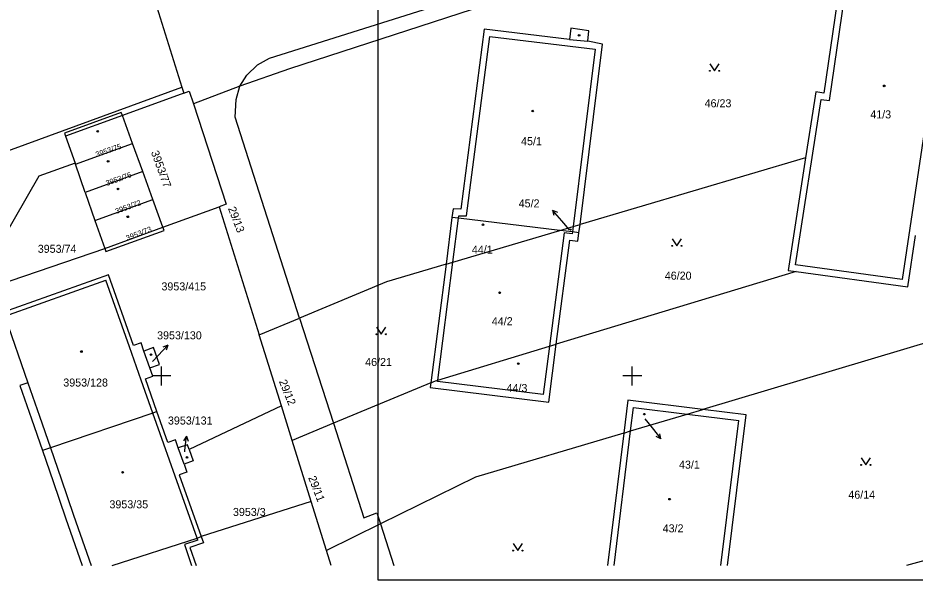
# Model space of a CAD drawing. Extents: x -599970 to -599524, y -1154772 to -1154457.
# Drawn here: x -599915.3 to -599820, y -1154771.7 to -1154712 of the extents above; entities that cross this region are included whole.
import ezdxf

# ---------------------------------------------------------------- set-up
doc = ezdxf.new("R2010")
doc.units = 0
for name, color, linetype in [('Z-KATASTRALNI MAPA', 7, 'Continuous'), ('Z-KRIZKY CTVERCOVE SITE', 7, 'Continuous'), ('Z-RAM ROZPISKA', 7, 'Continuous')]:
    doc.layers.add(name, color=color, linetype=linetype)

msp = doc.modelspace()

# ---------------------------------------------------------------- linework, layer by layer
at = {"layer": 'Z-KATASTRALNI MAPA'}
for p, q in [((-599829.05, -1154720.77), (-599826.27, -1154701.73)), ((-599900.66, -1154710.3), (-599897.83, -1154719.36)), ((-599867.61, -1154733.02), (-599865.13, -1154713.98)), ((-599865.13, -1154713.98), (-599853.93, -1154715.33)), ((-599856.68, -1154714.3), (-599854.73, -1154714.47)), ((-599853.93, -1154715.33), (-599856.28, -1154734.14)), ((-599897.64, -1154719.98), (-599904.16, -1154722.36)), ((-599897.83, -1154719.36), (-599897.64, -1154719.98)), ((-599891.67, -1154719.24), (-599896.62, -1154721.12)), ((-599832.65, -1154738.2), (-599829.92, -1154720.65)), ((-599829.92, -1154720.65), (-599829.05, -1154720.77)), ((-599904.16, -1154722.36), (-599910.2, -1154724.56)), ((-599903.08, -1154725.33), (-599904.16, -1154722.36)), ((-599818.78, -1154722.72), (-599821.34, -1154739.76)), ((-599909.15, -1154727.54), (-599903.08, -1154725.33)), ((-599902, -1154728.29), (-599903.08, -1154725.33)), ((-599909.15, -1154727.54), (-599909.19, -1154727.43)), ((-599908.11, -1154730.52), (-599909.15, -1154727.54)), ((-599831.6, -1154726.85), (-599855.55, -1154733.93)), ((-599902, -1154728.29), (-599908.11, -1154730.52)), ((-599900.93, -1154731.26), (-599902, -1154728.29)), ((-599908.11, -1154730.52), (-599907.07, -1154733.49)), ((-599907.07, -1154733.49), (-599900.93, -1154731.26)), ((-599899.85, -1154734.22), (-599900.93, -1154731.26)), ((-599899.85, -1154734.22), (-599893.87, -1154732.04)), ((-599893.87, -1154732.04), (-599889.62, -1154745.65)), ((-599857.49, -1154733.53), (-599858.475, -1154732.397)), ((-599858.475, -1154732.397), (-599857.957, -1154732.611)), ((-599858.475, -1154732.397), (-599858.335, -1154732.94)), ((-599869.15, -1154733.18), (-599869.78, -1154738.13)), ((-599869.05, -1154737.91), (-599868.46, -1154733.26)), ((-599868.46, -1154733.26), (-599868.42, -1154732.99)), ((-599868.42, -1154732.99), (-599867.61, -1154733.02)), ((-599907.07, -1154733.49), (-599906.02, -1154736.47)), ((-599906.02, -1154736.47), (-599899.85, -1154734.22)), ((-599856.68, -1154734.48), (-599857.49, -1154733.53)), ((-599856.28, -1154734.14), (-599856.35, -1154734.72)), ((-599855.66, -1154734.8), (-599855.55, -1154733.93)), ((-599857.25, -1154734.82), (-599858.81, -1154746.85)), ((-599856.38, -1154734.93), (-599857.25, -1154734.82)), ((-599856.35, -1154734.72), (-599856.38, -1154734.93)), ((-599917.6, -1154740.42), (-599906.02, -1154736.47)), ((-599869.78, -1154738.13), (-599876.11, -1154740)), ((-599869.78, -1154738.13), (-599871.4, -1154750.71)), ((-599870.66, -1154750.43), (-599869.05, -1154737.91)), ((-599821.34, -1154739.76), (-599832.65, -1154738.2)), ((-599832.6, -1154738.92), (-599858.08, -1154746.63)), ((-599905.63, -1154739.27), (-599916.8, -1154743.23)), ((-599916.65, -1154743.66), (-599905.91, -1154739.85)), ((-599903.4, -1154746.92), (-599905.91, -1154739.85)), ((-599876.11, -1154740), (-599885.34, -1154743.86)), ((-599889.62, -1154745.65), (-599885.34, -1154743.86)), ((-599885.34, -1154743.86), (-599881.75, -1154755.01)), ((-599812.77, -1154744.68), (-599842.5, -1154753.54)), ((-599887.27, -1154753.17), (-599889.62, -1154745.65)), ((-599900.37, -1154747.83), (-599899.346, -1154746.732)), ((-599899.346, -1154746.732), (-599899.872, -1154746.928)), ((-599899.346, -1154746.732), (-599899.505, -1154747.269)), ((-599858.81, -1154746.85), (-599858.08, -1154746.63)), ((-599902.15, -1154750.46), (-599903.4, -1154746.92)), ((-599901.24, -1154749.14), (-599901.87, -1154747.35)), ((-599858.81, -1154746.85), (-599859.48, -1154751.98)), ((-599900.96, -1154748.47), (-599900.37, -1154747.83)), ((-599900.92, -1154753.93), (-599902.15, -1154750.46)), ((-599871.4, -1154750.71), (-599870.91, -1154750.51)), ((-599870.68, -1154750.6), (-599870.66, -1154750.43)), ((-599859.48, -1154751.98), (-599870.68, -1154750.6)), ((-599914.2, -1154750.72), (-599912.97, -1154754.26)), ((-599871.4, -1154750.71), (-599881.75, -1154755.01)), ((-599887.27, -1154753.17), (-599897.06, -1154757.81)), ((-599886.13, -1154756.83), (-599887.27, -1154753.17)), ((-599850.18, -1154755.83), (-599849.87, -1154753.34)), ((-599849.87, -1154753.34), (-599844.17, -1154754.04)), ((-599912.97, -1154754.26), (-599911.8, -1154757.63)), ((-599899.75, -1154757.22), (-599900.92, -1154753.93)), ((-599844.17, -1154754.04), (-599838.68, -1154754.72)), ((-599881.75, -1154755.01), (-599886.13, -1154756.83)), ((-599848.65, -1154754.53), (-599847.89, -1154755.49)), ((-599840.58, -1154770.1), (-599838.68, -1154754.72)), ((-599850.91, -1154756.05), (-599866.67, -1154760.75)), ((-599851.94, -1154770.1), (-599850.18, -1154755.83)), ((-599847.89, -1154755.49), (-599846.966, -1154756.673)), ((-599846.966, -1154756.673), (-599847.077, -1154756.123)), ((-599898.54, -1154760.63), (-599899.75, -1154757.22)), ((-599897.363, -1154756.397), (-599897.664, -1154756.87)), ((-599897.52, -1154757.89), (-599897.363, -1154756.397)), ((-599897.363, -1154756.397), (-599897.167, -1154756.922)), ((-599884.11, -1154763.3), (-599886.13, -1154756.83)), ((-599846.966, -1154756.673), (-599847.472, -1154756.432)), ((-599911.8, -1154757.63), (-599910.66, -1154760.9)), ((-599897.61, -1154759.36), (-599898.22, -1154757.63)), ((-599897.54, -1154758.06), (-599897.52, -1154757.89)), ((-599910.66, -1154760.9), (-599909.34, -1154764.77)), ((-599896.21, -1154767.19), (-599898.54, -1154760.63)), ((-599866.67, -1154760.75), (-599876.75, -1154765.7)), ((-599884.11, -1154763.3), (-599895.79, -1154767.04)), ((-599882.48, -1154768.52), (-599884.11, -1154763.3)), ((-599909.34, -1154764.77), (-599907.46, -1154770.1)), ((-599876.75, -1154765.7), (-599882.48, -1154768.52)), ((-599896.13, -1154767.43), (-599897.56, -1154767.89)), ((-599896.13, -1154767.43), (-599896.21, -1154767.19)), ((-599897.56, -1154767.89), (-599896.8, -1154770.1)), ((-599881.99, -1154770.1), (-599882.48, -1154768.52)), ((-599817.19, -1154769.12), (-599820.88, -1154770.1))]:
    msp.add_line(p, q, dxfattribs=at)
for points in [[(-599891.67, -1154719.24), (-599890.93, -1154718.08), (-599889.79, -1154717), (-599888.53, -1154716.29), (-599840.69, -1154701.22)], [(-599833.96, -1154702.4), (-599865.59, -1154710.66), (-599886.42, -1154717.4), (-599891.67, -1154719.24)], [(-599827.27, -1154703.72), (-599829.64, -1154719.98), (-599830.51, -1154719.86), (-599830.65, -1154720.78), (-599831.6, -1154726.85)], [(-599856.68, -1154714.3), (-599865.74, -1154713.21), (-599868.22, -1154732.3), (-599869.03, -1154732.27), (-599869.15, -1154733.18)], [(-599854.73, -1154714.47), (-599854.63, -1154713.38), (-599856.53, -1154713.11), (-599856.68, -1154714.3)], [(-599855.55, -1154733.93), (-599853.16, -1154714.78), (-599854.73, -1154714.47)], [(-599841.76, -1154716.87), (-599841.26, -1154717.62), (-599840.76, -1154716.87)], [(-599926.88, -1154737.29), (-599920.92, -1154735.02), (-599917.44, -1154726.5), (-599897.83, -1154719.36)], [(-599897.64, -1154719.98), (-599897.06, -1154719.77), (-599896.62, -1154721.12)], [(-599885.34, -1154743.86), (-599892.18, -1154722.54), (-599892.08, -1154720.65), (-599891.67, -1154719.24)], [(-599896.62, -1154721.12), (-599893.12, -1154731.77), (-599893.87, -1154732.04)], [(-599904.16, -1154722.36), (-599904.28, -1154722.03), (-599910.32, -1154724.23), (-599910.2, -1154724.56), (-599909.19, -1154727.43)], [(-599909.19, -1154727.43), (-599913.05, -1154728.79), (-599918.31, -1154737.91)], [(-599831.6, -1154726.85), (-599833.45, -1154738.8), (-599832.6, -1154738.92)], [(-599857.69, -1154734.56), (-599868.46, -1154733.26), (-599869.15, -1154733.18)], [(-599906.02, -1154736.47), (-599905.9, -1154736.8), (-599899.73, -1154734.55), (-599899.85, -1154734.22)], [(-599857.69, -1154734.56), (-599856.28, -1154734.14), (-599855.55, -1154733.93)], [(-599869.78, -1154738.13), (-599869.05, -1154737.91), (-599857.69, -1154734.56)], [(-599858.08, -1154746.63), (-599856.65, -1154735.6), (-599855.77, -1154735.71), (-599855.66, -1154734.8)], [(-599855.66, -1154734.8), (-599856.35, -1154734.72), (-599857.69, -1154734.56)], [(-599832.6, -1154738.92), (-599820.75, -1154740.54), (-599819.93, -1154735.08)], [(-599845.76, -1154735.44), (-599845.26, -1154736.19), (-599844.76, -1154735.44)], [(-599901.87, -1154747.35), (-599902.17, -1154746.48), (-599902.98, -1154746.77), (-599905.63, -1154739.27)], [(-599916.65, -1154743.66), (-599914.2, -1154750.72), (-599915.05, -1154751.02), (-599913.82, -1154754.56), (-599912.66, -1154757.92)], [(-599877.17, -1154744.819), (-599876.67, -1154745.57), (-599876.17, -1154744.819)], [(-599871.4, -1154750.71), (-599871.46, -1154751.21), (-599858.88, -1154752.76), (-599858.08, -1154746.63)], [(-599901.24, -1154749.14), (-599900.21, -1154748.78), (-599900.84, -1154746.99), (-599901.87, -1154747.35)], [(-599870.91, -1154750.51), (-599870.66, -1154750.43), (-599858.81, -1154746.85)], [(-599900.49, -1154753.78), (-599901.72, -1154750.31), (-599900.93, -1154750.03), (-599901.24, -1154749.14)], [(-599842.5, -1154753.54), (-599850.48, -1154752.56), (-599850.91, -1154756.05)], [(-599900.49, -1154753.78), (-599900.92, -1154753.93), (-599911.8, -1154757.63), (-599912.66, -1154757.92)], [(-599898.22, -1154757.63), (-599898.52, -1154756.79), (-599899.32, -1154757.07), (-599900.49, -1154753.78)], [(-599850.91, -1154756.05), (-599850.18, -1154755.83), (-599844.17, -1154754.04), (-599842.5, -1154753.54)], [(-599839.88, -1154770.1), (-599837.9, -1154754.11), (-599842.5, -1154753.54)], [(-599881.75, -1154755.01), (-599878.53, -1154765.05), (-599877.13, -1154764.51), (-599876.75, -1154765.7)], [(-599850.91, -1154756.05), (-599852.64, -1154770.1)], [(-599912.66, -1154757.92), (-599911.51, -1154761.2), (-599910.19, -1154765.06), (-599908.43, -1154770.1)], [(-599897.06, -1154757.81), (-599897.25, -1154757.29), (-599898.22, -1154757.63)], [(-599897.06, -1154757.81), (-599896.63, -1154759.01), (-599897.61, -1154759.36)], [(-599825.7, -1154758.69), (-599825.2, -1154759.44), (-599824.7, -1154758.69)], [(-599897.61, -1154759.36), (-599897.31, -1154760.2), (-599898.11, -1154760.48), (-599895.79, -1154767.04)], [(-599876.75, -1154765.7), (-599875.34, -1154770.1)], [(-599905.26, -1154770.1), (-599896.21, -1154767.19), (-599895.79, -1154767.04)], [(-599895.79, -1154767.04), (-599895.55, -1154767.72), (-599896.98, -1154768.18), (-599896.32, -1154770.1)], [(-599862.66, -1154767.779), (-599862.16, -1154768.53), (-599861.66, -1154767.779)]]:
    msp.add_lwpolyline(points, dxfattribs=at)
for centre, radius in [((-599855.643, -1154713.85), 0.0875), ((-599841.76, -1154717.62), 0.05), ((-599840.76, -1154717.62), 0.05), ((-599823.243, -1154719.22), 0.0875), ((-599860.573, -1154721.89), 0.0875), ((-599906.783, -1154724.04), 0.0875), ((-599905.673, -1154727.22), 0.0875), ((-599904.623, -1154730.16), 0.0875), ((-599903.583, -1154733.11), 0.0875), ((-599865.863, -1154733.96), 0.0875), ((-599856.562, -1154734.47), 0.0586), ((-599845.76, -1154736.19), 0.05), ((-599844.76, -1154736.19), 0.05), ((-599864.093, -1154741.17), 0.0875), ((-599877.17, -1154745.57), 0.05), ((-599876.17, -1154745.57), 0.05), ((-599908.503, -1154747.41), 0.0875), ((-599901.113, -1154747.73), 0.0875), ((-599862.103, -1154748.69), 0.0875), ((-599848.713, -1154754.05), 0.0875), ((-599897.293, -1154758.64), 0.0875), ((-599904.133, -1154760.22), 0.0875), ((-599825.7, -1154759.44), 0.05), ((-599824.7, -1154759.44), 0.05), ((-599846.043, -1154763.07), 0.0875), ((-599862.66, -1154768.53), 0.05), ((-599861.66, -1154768.53), 0.05)]:
    msp.add_circle(centre, radius, dxfattribs=at)
at = {"layer": 'Z-KRIZKY CTVERCOVE SITE'}
for p, q in [((-599900, -1154751), (-599900, -1154749)), ((-599850, -1154751), (-599850, -1154749)), ((-599899, -1154750), (-599901, -1154750)), ((-599849, -1154750), (-599851, -1154750))]:
    msp.add_line(p, q, dxfattribs=at)
at = {"layer": 'Z-RAM ROZPISKA'}
msp.add_lwpolyline([(-599876.98, -1154456.65), (-599579.98, -1154456.65), (-599579.98, -1154771.65), (-599876.98, -1154771.65)], close=True, dxfattribs=at)

# ---------------------------------------------------------------- texts
at = {"layer": 'Z-KATASTRALNI MAPA'}
for s, p in [('46/23', (-599842.317, -1154721.49)), ('41/3', (-599824.721, -1154722.67)), ('45/1', (-599861.811, -1154725.51)), ('45/2', (-599862.064, -1154732.11)), ('3953/74', (-599913.146, -1154736.93)), ('44/1', (-599867.038, -1154737.01)), ('46/20', (-599846.547, -1154739.78)), ('3953/415', (-599900.01, -1154740.92)), ('44/2', (-599864.919, -1154744.61)), ('3953/130', (-599900.47, -1154746.11)), ('46/21', (-599878.369, -1154748.94)), ('3953/128', (-599910.434, -1154751.12)), ('44/3', (-599863.355, -1154751.7)), ('3953/131', (-599899.32, -1154755.15)), ('43/1', (-599845.04, -1154759.83)), ('46/14', (-599827.053, -1154763.02)), ('3953/35', (-599905.533, -1154764.04)), ('3953/3', (-599892.415, -1154764.85)), ('43/2', (-599846.772, -1154766.59))]:
    msp.add_text(s, height=0.85, dxfattribs=at).set_placement(p)
for s, height, rotation, p in [('3953/75', 0.57, 19, (-599906.898, -1154726.79)), ('3953/77', 0.85, 290, (-599901.137, -1154726.253)), ('3953/76', 0.57, 20, (-599905.803, -1154729.843)), ('3953/72', 0.57, 20, (-599904.796, -1154732.811)), ('29/13', 0.85, 291, (-599892.952, -1154732.225)), ('3953/73', 0.57, 21, (-599903.65, -1154735.66)), ('29/12', 0.85, 292, (-599887.545, -1154750.571)), ('29/11', 0.85, 291, (-599884.434, -1154760.778))]:
    msp.add_text(s, height=height, rotation=rotation, dxfattribs=at).set_placement(p)

doc.saveas('drawing.dxf')
